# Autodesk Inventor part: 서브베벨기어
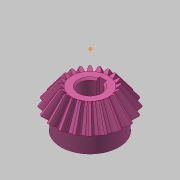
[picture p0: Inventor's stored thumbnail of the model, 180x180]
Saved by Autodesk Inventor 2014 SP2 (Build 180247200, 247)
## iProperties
Created: 2018-09
Part Number: 서브베벨기어
Material: 강철, 탄소
Document SubType Name: Modeling
Categories: <?xml version="1.0" encoding="UTF-16"?> <MemberInstance><Categories><FamilyTemplate><FamilyTemplateParameter ValueType="xs:double" Id="1" ObjectReferenceKey="da
Mass: 135.037 g
Surface Area: 63.6494 cm^2
Volume: 17.1585 cm^3
Density: 7.87 g/cm^3
Appearance: 분홍색
CustomPartVersion: 1
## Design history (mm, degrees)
node "맨 위 점"
node "메쉬 평면2"
sketch "톱니 본체 스케치"
  geometry: L1 (0, 0)-(18.003, -31.331); L2 (18.003, -31.331)-(21.664, -28.891); L3 (21.664, -28.891)-(0, 0); L4 (20, -30)-(0, 0); L5 (10.813, -18.818)-(13.012, -17.352); L6 (18.003, -31.331)-(10.813, -18.818); L7 (21.664, -28.891)-(13.012, -17.352); L8 (0, -39.387)-(0, 6.564) reference; L9 (0, -30)-(21.664, -30)
  constraints: 16 end point, 4 point on line, 3 perpendicular, 2 collinear, 1 horizontal alignment, 1 vertical alignment
  dimensions: "d0" = 40 diameter of L4.start L8 (= da_de); "d1" = 36.00616 diameter of L1.end L8 (= da_dfe); "d2" = 43.3282 diameter of L2.end L8 (= da_dae); "d3" = 14.4 distance between parallel lines of L2 L5 (= da_b); "d4" = 28.8906 vertical distance of L2.end L1.start (= da_ve)
revolve "톱니 본체" sketch "톱니 본체 스케치" stored, may be unused: angle "d5" = 90 deg
node "시작점"
node "톱니 평면"
sketch "시작 스케치"
  geometry: L1 (0, -23.505)-(0, 10.645) reference; L2 (-0.834, -2.928)-(0.834, -2.928); A1 r 8.898 centre (-9.698, -3.713) between (-0.834, -2.928) and (-3.903, 3.04); A2 r 8.898 centre (9.698, -3.713) between (3.903, 3.04) and (0.834, -2.928); A3 r 27.357 centre (0, -24.037) between (3.903, 3.04) and (-3.903, 3.04); 1 further point
  constraints: 6 point on circle, 3 centre point, 3 symmetric about line, 2 end point, 1 coincident, 1 perpendicular, 1 other
  dimensions: "d7" = 8.89846 radius of A1 (= fd_rr); "d8" = 9.69794 horizontal distance of point (0, -24.037) A1.centre (= fd_x); "d9" = 20.32439 vertical distance of point (0, -24.037) A1.centre (= fd_y); "d57" = 27.35701 radius of A3 (= 0.5 x fd_dva + 0.3 x da_he); "d58" = 21.10901 distance from line of A3.centre L2 (= 0.5 x fd_dva - 1.12 x da_he)
node "끝점"
  node "끝 평면"
sketch "3D 스케치 오른쪽"
  node "Helical Curve Right" dims "d65" = 229.90621 (computed from da_dm, da_delta, da_beta), "d66" = 31.5, "d67" = 40 (= da_de), "d68" = -5.88003 (= -da_delta), "d69" = 12.16458 (computed from fd_loft, da_delta)
node "끝 평면 오른쪽"
sketch "끝 스케치 오른쪽"
  geometry: L1 (0, -22.649)-(0, 12.15) reference; L2 (-0.497, -1.72)-(0.497, -1.72); A1 r 5.299 centre (-5.775, -2.187) between (-0.497, -1.72) and (-2.324, 1.834); A2 r 5.299 centre (5.775, -2.187) between (2.324, 1.834) and (0.497, -1.72); A3 r 16.291 centre (0, -14.29) between (2.324, 1.834) and (-2.324, 1.834); 1 further point
  constraints: 6 point on circle, 3 centre point, 3 symmetric about line, 2 end point, 1 coincident, 1 perpendicular, 1 other
  dimensions: "d70" = 5.77526 horizontal distance of A3.centre A1.centre (computed from fd_x, fd_ratio); "d71" = 12.10346 vertical distance of point (0, -14.29) A1.centre (computed from fd_y, fd_ratio); "d72" = 5.29916 radius of A1 (computed from fd_rr, fd_ratio); "d73" = 12.57071 distance from line of point (0, -14.29) L2 (computed from d58, fd_ratio); "d74" = 16.29149 radius of A3 (computed from d57, fd_ratio)
feature "로프트 오른쪽" sketch "끝 스케치 오른쪽" dims "d75" = 0, "d77" = 0, "d79" = 0, "d80" = 90 deg, "d85" = 20, "d92" = 90 deg, "d93" = 90 deg, "da_teethtype" = 0 [user parameter]
sketch "3D 스케치 왼쪽"
  node "Helical Curve Left" dims "d26" = 229.90621 (computed from da_dm, da_delta, da_beta), "d27" = 12.16458 (computed from fd_loft, da_delta), "d28" = 40 (= da_de), "d29" = -5.88003 (= -da_delta)
node "끝 평면 왼쪽"
sketch "끝 스케치 왼쪽" dims "d56" = 10.82768 (derived)
  geometry: L1 (0, -35.087)-(0, 18.089) reference; L2 (-0.497, -1.716)-(0.497, -1.716); A1 r 5.299 centre (-5.775, -2.183) between (-0.497, -1.716) and (-2.324, 1.838); A2 r 5.299 centre (5.775, -2.183) between (2.324, 1.838) and (0.497, -1.716); A3 r 16.291 centre (0, -14.287) between (2.324, 1.838) and (-2.324, 1.838); 2 further points; 1 other entity
  constraints: 6 point on circle, 3 centre point, 3 symmetric about line, 2 end point, 1 coincident, 2 other
  dimensions: "d30" = 5.29916 radius of A1 (computed from fd_rr, fd_ratio); "d31" = 5.77526 horizontal distance of point (0, -14.287) A1.centre (computed from fd_x, fd_ratio); "d32" = 12.10346 vertical distance of A1.centre point (0, -14.287) (computed from fd_y, fd_ratio); "d61" = 16.29149 radius of A3 (computed from d57, fd_ratio); "d62" = 12.57071 distance from line of point (0, -14.287) L2 (computed from d58, fd_ratio)
feature "로프트 왼쪽" sketch "끝 스케치 왼쪽" dims "d35" = 0, "d37" = 0, "d39" = 0, "d40" = 90 deg, "d84" = 10, "d90" = 90 deg, "d91" = 90 deg, "da_teethtype" = 0 [user parameter]
sketch "본체 스케치"
  geometry: L1 (0, -35.038)-(0, -19.531) reference; L2 (18.003, -31.331)-(10.813, -18.818) reference; L3 (10.813, -18.818)-(0, -18.818); L4 (18.003, -31.331)-(0, -31.331)
  constraints: 4 end point, 2 perpendicular, 2 point on line
revolve "본체 고정" sketch "본체 스케치" stored, may be unused: angle "d46" = 90 deg
feature "피치 지름" dims angle "d47" = 90 deg
sketch "스케치8"
  geometry: C1 r 17 at (0, 0); 1 further point
  constraints: 1 centre point, 1 coincident
  dimensions: "d94" = 34 diameter of C1
extrude "돌출1" join sketch "스케치8" distance "d95" = 10; taper "d96" = 0 deg
sketch "스케치9"
  geometry: 1 further point
hole "구멍1" sketch "스케치9" at (0, 0) diameter "d97" = 12; stored, may be unused: countersink angle "d101" = 90 deg, drill point angle "d103" = 118 deg; dims "d98" = 6, "d99" = 4, "d100" = 2, "d102" = 8
sketch "스케치10"
  geometry: 1 further point
sketch "스케치11"
  geometry: 1 further point
sketch "스케치12"
  geometry: L1 (-2, 5.657)-(-2, 7.8); L2 (-2, 7.8)-(2, 7.8); L3 (2, 7.8)-(2, 5.657); A1 r 6 centre (0, 0) between (-2, 5.657) and (2, 5.657) reference; 1 further point
  constraints: 6 end point, 2 parallel, 2 point on circle, 1 perpendicular, 1 vertical
  dimensions: "d104" = 4 distance of L1.end L2.end; "d105" = 13.8 dimension on A1 L2
extrude "돌출2" cut sketch "스케치12" stored distance "d106" = 7; taper "d107" = 0 deg
chamfer "모따기1" distance "d108" = 1; stored, may be unused: second distance "d109" = 2, angle "d110" = 45 deg
body "Solid1"
feature "로프트" dims "d17" = 0, "d18" = 90 deg, "d19" = 0, "d20" = 90 deg, "d89" = 0, "da_teethtype" = 0 [user parameter]
pattern_circular "원형 패턴" dims angle "d22" = 360 deg, "d88" = 0, "da_teethtype" = 0 [user parameter]
pattern_circular "원형 패턴 오른쪽" dims angle "d82" = 360 deg, "da_teethtype" = 0 [user parameter]
pattern_circular "원형 패턴 왼쪽" dims angle "d42" = 360 deg, "da_teethtype" = 0 [user parameter]
sketch "끝 스케치"
  geometry: L1 (0, -15.359)-(0, 6.983) reference; L2 (-0.497, -1.72)-(0.497, -1.72); A1 r 5.299 centre (-5.775, -2.187) between (-0.497, -1.72) and (-2.324, 1.834); A2 r 5.299 centre (5.775, -2.187) between (2.324, 1.834) and (0.497, -1.72); A3 r 16.291 centre (0, -14.29) between (2.324, 1.834) and (-2.324, 1.834); 1 further point
  constraints: 6 point on circle, 3 centre point, 3 symmetric about line, 2 end point, 1 coincident, 1 other
  dimensions: "d12" = 5.29916 radius of A1 (computed from fd_rr, fd_ratio); "d15" = 5.77526 horizontal distance of A1.centre point (0, -14.29) (computed from fd_x, fd_ratio); "d16" = 12.10346 vertical distance of A1.centre point (0, -14.29) (computed from fd_y, fd_ratio); "d59" = 16.29149 radius of A3 (computed from d57, fd_ratio); "d60" = 12.57071 distance from line of A3.centre L2 (computed from d58, fd_ratio)
sketch "Sketch6"
  geometry: L1 (20, -30)-(0, 0) reference; L2 (0, -37.8)-(0, 6.3) reference
body "Srf1"
other parameters: "da_b" = 14.4 [user parameter; used in 2 equation terms], "da_de" = 40 [user parameter; used in 4 equation terms], "da_dae" = 43.3282 [user parameter; used in 2 equation terms], "da_dfe" = 36.00616 [user parameter; used in 1 equation term], "da_le" = 36.05551 [user parameter; used in 1 equation term], "da_omega" = 90 deg [user parameter; used in 1 equation term], "da_beta" = 0 [user parameter; used in 2 equation terms], "da_delta" = 5.88003 [user parameter; used in 8 equation terms], "da_alpha" = 20 deg [user parameter; used in 2 equation terms], "da_he" = 4.4 [user parameter; used in 4 equation terms], "da_ve" = 28.8906 [user parameter; used in 1 equation term], "fd_dv" = 48.07402 (computed from da_de, da_delta) [user parameter; used in 1 equation term], "fd_dva" = 52.07402 (computed from da_dae, da_delta) [user parameter; used in 3 equation terms], "fd_dvb" = 45.1748 (computed from fd_dv, da_alpha) [user parameter; used in 2 equation terms], "da_zv" = 240.37008 [user parameter; used in 1 equation term], "fd_loft" = 14.62 (= da_b + 0.05 x da_he) [user parameter; used in 4 equation terms], "fd_ratio" = 5.95514 (computed from da_le, fd_loft) [user parameter; used in 15 equation terms], "fd_rr" = 8.89846 (computed from fd_dd, fd_dvb) [user parameter; used in 6 equation terms], "fd_angle" = 0.66075 (computed from da_zv) [user parameter; used in 4 equation terms], "fd_x1" = 1.58709 (computed from da_dvw, fd_angle) [user parameter; used in 1 equation term], "fd_y1" = 23.98456 (computed from da_dvw, fd_angle) [user parameter; used in 1 equation term], "fd_x2" = 8.11084 (computed from fd_rr, fd_angle2, fd_angle) [user parameter; used in 1 equation term], "fd_y2" = 3.66016 (computed from fd_rr, fd_angle2, fd_angle) [user parameter; used in 1 equation term], "fd_x" = 9.69794 (= fd_x1 + fd_x2) [user parameter; used in 4 equation terms], "fd_y" = 20.32439 (= fd_y1 - fd_y2) [user parameter; used in 4 equation terms], "fd_angle2" = 3.57832 (computed from fd_dvb, fd_dd, da_alpha) [user parameter; used in 2 equation terms], "fd_dd" = 48.55402 (= fd_dva - 0.8 x da_he) [user parameter; used in 2 equation terms], "da_dvw" = 48.07402 [user parameter; used in 2 equation terms], "d11" = 14.62 (= fd_loft), "da_dm" = 32.01232 [user parameter; used in 2 equation terms], "da_x" = 0 [user parameter], "da_m" = 2 [user parameter], "d48" = 0, "d49" = 0, "d50" = 90 deg (= da_omega), "d51" = 9 deg (computed from da_z), "d52" = 0, "d53" = 0, "d54" = 0
